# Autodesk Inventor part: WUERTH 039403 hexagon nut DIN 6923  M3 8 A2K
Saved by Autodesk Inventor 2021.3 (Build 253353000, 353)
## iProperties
Created: 2023-03
Part Number: WUERTH 039403 hexagon nut DIN 6923  M3 8 A2K
Material: Generic
Document SubType Name: Modeling
Designer: AdminForWorker
Density: 1 g/cm^3
Appearance: Default
Title: WUERTH 039403 hexagon nut DIN 6923  M3 8 A2K
Author: AdminForWorker
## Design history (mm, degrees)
feature "Body1"
body "Solid1"
